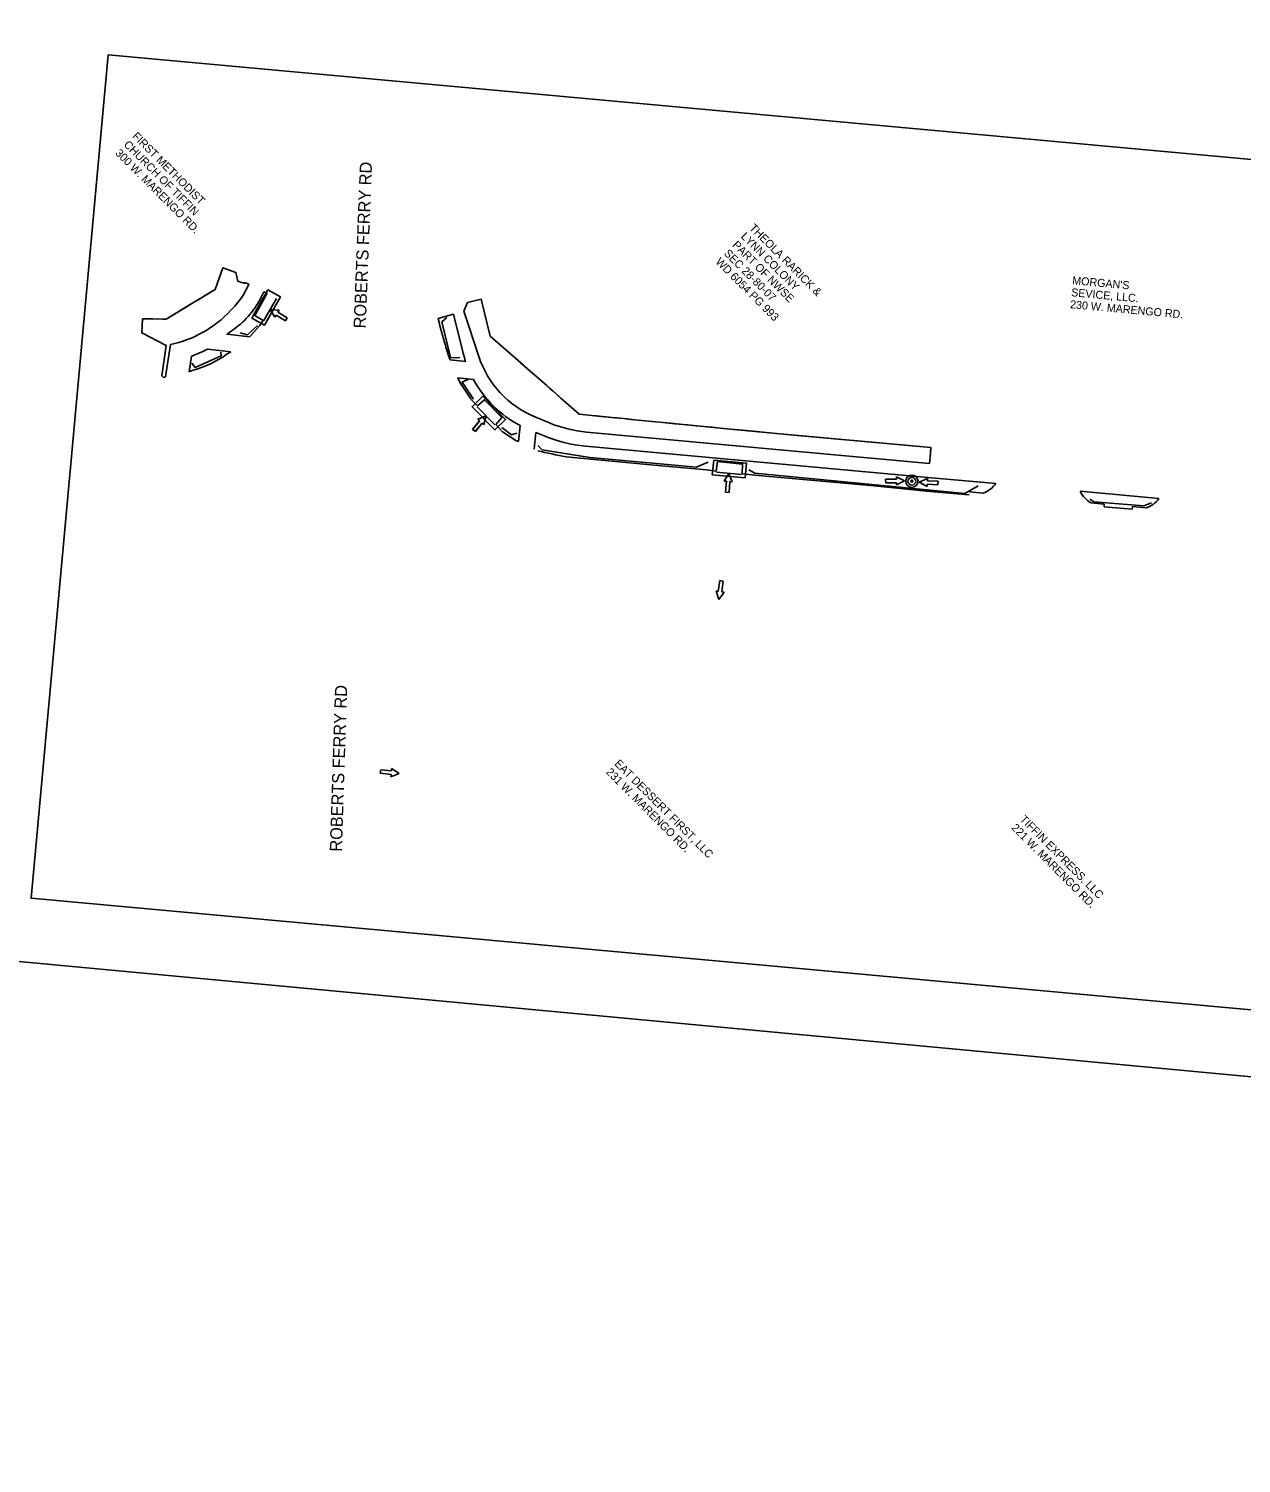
# Model space of a CAD drawing. Extents: x 20499351 to 20505779, y 7953198 to 7954637.
# Drawn here: x 20499884 to 20500313, y 7953707 to 7954215 of the extents above; entities that cross this region are included whole.
import ezdxf

# ---------------------------------------------------------------- set-up
doc = ezdxf.new("R2010")
doc.units = 0
for name, color, linetype in [('Draft_DNC', 7, 'Continuous'), ('dsnCellElements', 7, 'Continuous'), ('ErosionControl', 7, 'Continuous'), ('NamedBoundary', 7, 'Continuous'), ('Seeding', 7, 'Continuous'), ('Text', 7, 'Continuous')]:
    doc.layers.add(name, color=color, linetype=linetype)

msp = doc.modelspace()

# ---------------------------------------------------------------- linework, layer by layer
at = {"layer": 'Draft_DNC'}
msp.add_lwpolyline([(20501791.06, 7953833.84), (20501779.66, 7953706.56), (20499351.13, 7953933.78), (20499411.85, 7954636.65), (20501855.07, 7954405.25), (20501814.1, 7954091.19), (20501791.1, 7953834.34)], dxfattribs=at)
at = {"layer": 'dsnCellElements'}
for p, q in [((20499970.77, 7954112.56), (20499969.06, 7954115.26)), ((20499969.06, 7954115.26), (20499972.25, 7954115.01)), ((20499971.18, 7954113.24), (20499970.77, 7954112.56)), ((20499974.45, 7954111.26), (20499971.18, 7954113.24)), ((20499972.25, 7954115.01), (20499971.84, 7954114.33)), ((20499971.84, 7954114.33), (20499975.11, 7954112.35)), ((20499975.11, 7954112.35), (20499974.45, 7954111.26)), ((20500042.6, 7954076.28), (20500045.51, 7954077.59)), ((20500042.63, 7954076.37), (20500045.57, 7954077.65)), ((20500045.51, 7954077.59), (20500044.81, 7954074.47)), ((20500045.57, 7954077.65), (20500044.83, 7954074.53)), ((20500040.79, 7954072.94), (20500043.24, 7954075.86)), ((20500041.76, 7954072.12), (20500040.79, 7954072.94)), ((20500040.8, 7954072.82), (20500043.21, 7954075.77)), ((20500041.79, 7954072.01), (20500040.8, 7954072.82)), ((20500044.22, 7954075.04), (20500041.76, 7954072.12)), ((20500044.2, 7954074.97), (20500041.79, 7954072.01)), ((20500043.21, 7954075.77), (20500042.6, 7954076.28)), ((20500043.24, 7954075.86), (20500042.63, 7954076.37)), ((20500044.81, 7954074.47), (20500044.2, 7954074.97)), ((20500044.83, 7954074.53), (20500044.22, 7954075.04)), ((20500129.92, 7954054.47), (20500131.56, 7954057.22)), ((20500131.56, 7954057.22), (20500132.77, 7954054.26)), ((20500130.71, 7954054.41), (20500129.92, 7954054.47)), ((20500130.42, 7954050.61), (20500130.71, 7954054.41)), ((20500131.98, 7954054.32), (20500131.69, 7954050.51)), ((20500132.77, 7954054.26), (20500131.98, 7954054.32)), ((20500187.14, 7954055.13), (20500190.95, 7954055.2)), ((20500187.16, 7954053.86), (20500187.14, 7954055.13)), ((20500190.97, 7954053.92), (20500187.16, 7954053.86)), ((20500190.94, 7954055.99), (20500193.83, 7954054.61)), ((20500190.95, 7954055.2), (20500190.94, 7954055.99)), ((20500190.99, 7954053.13), (20500190.97, 7954053.92)), ((20500193.83, 7954054.61), (20500190.99, 7954053.13)), ((20500199.03, 7954054.12), (20500201.95, 7954055.43)), ((20500201.83, 7954052.57), (20500199.03, 7954054.12)), ((20500201.86, 7954053.37), (20500201.83, 7954052.57)), ((20500205.67, 7954053.21), (20500201.86, 7954053.37)), ((20500201.95, 7954055.43), (20500201.91, 7954054.64)), ((20500201.91, 7954054.64), (20500205.73, 7954054.48)), ((20500205.73, 7954054.48), (20500205.67, 7954053.21)), ((20500131.69, 7954050.51), (20500130.42, 7954050.61)), ((20500127.83, 7954015.45), (20500128.33, 7954019.23)), ((20500128.33, 7954019.23), (20500129.59, 7954019.06)), ((20500129.59, 7954019.06), (20500129.09, 7954015.28)), ((20500128.08, 7954012.53), (20500127.04, 7954015.55)), ((20500127.04, 7954015.55), (20500127.83, 7954015.45)), ((20500129.88, 7954015.18), (20500128.08, 7954012.53)), ((20500129.09, 7954015.28), (20500129.88, 7954015.18)), ((20500008.1, 7953951), (20500008.24, 7953952.26)), ((20500011.89, 7953950.58), (20500008.1, 7953951)), ((20500008.24, 7953952.26), (20500012.03, 7953951.84)), ((20500014.81, 7953950.9), (20500011.8, 7953949.79)), ((20500011.8, 7953949.79), (20500011.89, 7953950.58)), ((20500012.03, 7953951.84), (20500012.12, 7953952.63)), ((20500012.12, 7953952.63), (20500014.81, 7953950.9))]:
    msp.add_line(p, q, dxfattribs=at)
at = {"layer": 'ErosionControl'}
for p, q in [((20499961.16, 7954123.52), (20499961.48, 7954124.24)), ((20499966.43, 7954120.77), (20499966.78, 7954121.56)), ((20499966.78, 7954121.56), (20499968.01, 7954121.01)), ((20499971.29, 7954119.15), (20499966.84, 7954111.38)), ((20499955.04, 7954114.91), (20499956.53, 7954116.5)), ((20500028.62, 7954112.09), (20500033.97, 7954113.6)), ((20500037.46, 7954099.8), (20500033.97, 7954113.6)), ((20500033.97, 7954113.6), (20500037.46, 7954099.8)), ((20500043, 7954098.63), (20500037.71, 7954114.69)), ((20499932.05, 7954091.4), (20499933.71, 7954102.88)), ((20499933.71, 7954102.88), (20499932.05, 7954091.4)), ((20499941.2, 7954098.76), (20499940.4, 7954093.25)), ((20499955.15, 7954100.28), (20499946.86, 7954101.23)), ((20499946.86, 7954101.23), (20499955.15, 7954100.28)), ((20500032.84, 7954097.43), (20500032.54, 7954098.2)), ((20500038.34, 7954096.8), (20500032.84, 7954097.43)), ((20499940.4, 7954093.25), (20499941.42, 7954093.64)), ((20499941.42, 7954093.64), (20499940.4, 7954093.25)), ((20499932.05, 7954091.4), (20499931.33, 7954091.18)), ((20500036.44, 7954089.34), (20500035.55, 7954091.08)), ((20500041.12, 7954090.44), (20500035.55, 7954091.08)), ((20500042.48, 7954081.13), (20500040.14, 7954083.57)), ((20500040.14, 7954083.57), (20500042.48, 7954081.13)), ((20500048.68, 7954074.46), (20500042.46, 7954080.84)), ((20500068.03, 7954075.1), (20500062.84, 7954077.25)), ((20500057, 7954068.52), (20500057.61, 7954074.18)), ((20500063.18, 7954071.7), (20500062.55, 7954065.83)), ((20500066.12, 7954070.48), (20500063.18, 7954071.7)), ((20500066.12, 7954070.48), (20500063.18, 7954071.7)), ((20500202.65, 7954060.78), (20500081.18, 7954071.85)), ((20500202.05, 7954055.82), (20500080.74, 7954066.87)), ((20500202.76, 7954061.85), (20500202.65, 7954060.78)), ((20500136.05, 7954056.79), (20500127.22, 7954057.7)), ((20500226.17, 7954053.62), (20500202.05, 7954055.82)), ((20500201.61, 7954050.95), (20500216.77, 7954049.63)), ((20500216.85, 7954050.63), (20500221.68, 7954050.21)), ((20500256.04, 7954050.87), (20500283.97, 7954048.3)), ((20500264.61, 7954046.35), (20500259.89, 7954046.76)), ((20500274.52, 7954044.51), (20500264.52, 7954045.36)), ((20500279.54, 7954045.03), (20500274.61, 7954045.45))]:
    msp.add_line(p, q, dxfattribs=at)
for points in [[(20499931.33, 7954091.18), (20499930.64, 7954091.73), (20499932.26, 7954102.58), (20499923.57, 7954106.97), (20499923.9, 7954111.96), (20499932.19, 7954111.86), (20499936.85, 7954114.68), (20499940.55, 7954116.91), (20499944.11, 7954119.05), (20499945.84, 7954120.1), (20499947.93, 7954121.36), (20499949.54, 7954122.33), (20499952.26, 7954130.07), (20499956.97, 7954128.41), (20499957.58, 7954125.3), (20499958.93, 7954124.81), (20499959.55, 7954124.7), (20499959.85, 7954124.53), (20499960.13, 7954124.84), (20499961.47, 7954124.25)], [(20499968.01, 7954121.01), (20499963.61, 7954113.2), (20499966.58, 7954111.4)], [(20500037.71, 7954114.69), (20500039, 7954117.73), (20500043.86, 7954118.89), (20500046.99, 7954105.86), (20500054.19, 7954099.56), (20500058.66, 7954095.65), (20500065.77, 7954089.43), (20500068.3, 7954087.22), (20500069.35, 7954086.3), (20500070.87, 7954084.98), (20500072.09, 7954083.91), (20500078.6, 7954078.22), (20500083.09, 7954077.76), (20500086.33, 7954077.43), (20500088.94, 7954077.16), (20500091.19, 7954076.94), (20500091.91, 7954076.86), (20500094.21, 7954076.63), (20500097, 7954076.35), (20500100.74, 7954075.98), (20500105.59, 7954075.5), (20500111, 7954074.96), (20500115.39, 7954074.53), (20500121.42, 7954073.95), (20500128.45, 7954073.27), (20500135.78, 7954072.57), (20500147.21, 7954071.5), (20500203.2, 7954066.35), (20500203.06, 7954064.92), (20500202.86, 7954062.84), (20500202.75, 7954061.85), (20500202.76, 7954061.85)], [(20500031.72, 7954112.5), (20500029.87, 7954110.88), (20500033.02, 7954098.33), (20500036.24, 7954098.12)], [(20499961.73, 7954105.57), (20499953.82, 7954106.48), (20499957.03, 7954108.89)], [(20499958.39, 7954107.05), (20499961.03, 7954106.31), (20499964.61, 7954109.64)], [(20499966.58, 7954111.4), (20499965.38, 7954109.56), (20499962.15, 7954105.96), (20499961.73, 7954105.57)], [(20499941.29, 7954096.26), (20499942.55, 7954094.7), (20499951.74, 7954098.89), (20499951.64, 7954100.18)], [(20499953.87, 7954099.52), (20499954.99, 7954100.19), (20499955.12, 7954100.29)], [(20500039.37, 7954090.6), (20500037.08, 7954089.51), (20500041.15, 7954083.54)], [(20500042.48, 7954081.13), (20500045.03, 7954083.31), (20500051.14, 7954077.06), (20500049, 7954074.51)], [(20500049, 7954074.51), (20500051.43, 7954071.95), (20500056.15, 7954068.91), (20500057, 7954068.52)], [(20500051.11, 7954073.53), (20500054.61, 7954070.93), (20500056.44, 7954071.5)], [(20500063.92, 7954067.15), (20500065.41, 7954065.59), (20500082.38, 7954062.87), (20500109.87, 7954060.35), (20500120.05, 7954059.46), (20500124.2, 7954061.22)], [(20500073.94, 7954063.07), (20500103.94, 7954060.2), (20500123.68, 7954058.43), (20500127.04, 7954058.06)], [(20500127.04, 7954058.06), (20500127.52, 7954061.41), (20500136.42, 7954060.54), (20500136.28, 7954057.11)], [(20500136.28, 7954057.11), (20500143.33, 7954056.36), (20500183.05, 7954052.76), (20500201.61, 7954050.95)], [(20500138.72, 7954058.46), (20500140.82, 7954057.3), (20500215.22, 7954050.15), (20500219.97, 7954052.8)], [(20500259.44, 7954048.12), (20500260.95, 7954047.15), (20500278.64, 7954045.76), (20500281.36, 7954046.81)]]:
    msp.add_lwpolyline(points, dxfattribs=at)
for points in [[(20499968.23, 7954122.26), (20499962.59, 7954112.25), (20499967.04, 7954109.75), (20499972.68, 7954119.75)], [(20500044.42, 7954084.52), (20500052.46, 7954076.29), (20500048.69, 7954072.6), (20500040.64, 7954080.84)], [(20500126.22, 7954061.95), (20500137.84, 7954060.81), (20500137.33, 7954055.6), (20500125.71, 7954056.74)]]:
    msp.add_lwpolyline(points, close=True, dxfattribs=at)
for radius in [2.19, 1.38, 1.38, 0.333]:
    msp.add_circle((20500196.42, 7954054.44), radius, dxfattribs=at)
for centre, radius, start, end in [((20499938.28, 7954133.59), 25, 316.8794, 338.0615), ((20499938.28, 7954133.59), 25, 316.8794, 336.2589), ((20499938.97, 7954132.85), 30, 307.0003, 336.2589), ((20499925.67, 7954142.06), 40, 281.6016, 317.2577), ((20499925.67, 7954142.06), 40, 281.6016, 317.2577), ((20499925.67, 7954142.06), 46, 289.7337, 297.437), ((20499925.67, 7954142.06), 46, 289.7337, 297.437), ((20500076.24, 7954109.58), 40, 194.1598, 198.6373), ((20500076.24, 7954109.58), 35, 198.233, 247.4817), ((20500076.24, 7954109.58), 40, 208.5871, 242.24), ((20500085.27, 7954116.67), 45, 247.4817, 264.7944), ((20500085.27, 7954116.67), 50, 247.4814, 264.8052), ((20500085.27, 7954116.67), 50, 247.4814, 264.8052), ((20500218.11, 7954059.55), 10, 290.8655, 323.6405), ((20500264.98, 7954055.36), 10, 206.6445, 239.2845), ((20500276.04, 7954054.39), 10, 290.563, 322.4475)]:
    msp.add_arc(centre, radius, start, end, dxfattribs=at)
for centre, major_axis, ratio, start_param, end_param in [((20499930.7, 7954132.48), (40.08, -4.21), 0.999939, 5.086579, 5.429975), ((20499930.7, 7954132.48), (40.08, -4.21), 0.999939, 5.086579, 5.429975), ((20500101.16, 7954128.32), (47.26, -79.5), 0.816879, 4.717117, 4.7912), ((20500101.16, 7954128.32), (47.26, -79.5), 0.816879, 4.717117, 4.7912), ((20500118.18, 7954291.91), (234.67, -29.43), 0.985398, 4.603689, 4.647146)]:
    msp.add_ellipse(centre, major_axis=major_axis, ratio=ratio, start_param=start_param, end_param=end_param, dxfattribs=at)
msp.add_open_spline([(20500032.54, 7954098.2), (20500032.12, 7954099.31), (20500030.86, 7954103.62), (20500029.54, 7954108.18), (20500028.72, 7954111.66), (20500028.62, 7954112.09)], degree=3, dxfattribs=at)
msp.add_open_spline([(20500032.54, 7954098.2), (20500032.12, 7954099.31), (20500030.86, 7954103.62), (20500029.54, 7954108.18), (20500028.72, 7954111.66), (20500028.62, 7954112.09)], degree=3, dxfattribs=at)
at = {"layer": 'NamedBoundary'}
msp.add_lwpolyline([(20499911.73, 7954205.45), (20499884.39, 7953906.7), (20500820.97, 7953820.99), (20500848.31, 7954119.74)], close=True, dxfattribs=at)
at = {"layer": 'Seeding'}
for p, q in [((20499961.16, 7954123.52), (20499961.48, 7954124.24)), ((20499966.43, 7954120.77), (20499966.78, 7954121.56)), ((20499966.78, 7954121.56), (20499968.01, 7954121.01)), ((20499955.04, 7954114.91), (20499956.53, 7954116.5)), ((20500028.62, 7954112.09), (20500033.97, 7954113.6)), ((20500037.46, 7954099.8), (20500033.97, 7954113.6)), ((20500033.97, 7954113.6), (20500037.46, 7954099.8)), ((20500043, 7954098.63), (20500037.71, 7954114.69)), ((20499932.05, 7954091.4), (20499933.71, 7954102.88)), ((20499933.71, 7954102.88), (20499932.05, 7954091.4)), ((20499941.2, 7954098.76), (20499940.4, 7954093.25)), ((20499955.15, 7954100.28), (20499946.86, 7954101.23)), ((20499946.86, 7954101.23), (20499955.15, 7954100.28)), ((20500032.84, 7954097.43), (20500032.54, 7954098.2)), ((20500038.34, 7954096.8), (20500032.84, 7954097.43)), ((20499940.4, 7954093.25), (20499941.42, 7954093.64)), ((20499941.42, 7954093.64), (20499940.4, 7954093.25)), ((20499932.05, 7954091.4), (20499931.33, 7954091.18)), ((20500036.44, 7954089.34), (20500035.55, 7954091.08)), ((20500041.12, 7954090.44), (20500035.55, 7954091.08)), ((20500042.48, 7954081.13), (20500040.14, 7954083.57)), ((20500040.14, 7954083.57), (20500042.48, 7954081.13)), ((20500068.03, 7954075.1), (20500062.84, 7954077.25)), ((20500057, 7954068.52), (20500057.61, 7954074.18)), ((20500063.18, 7954071.7), (20500062.55, 7954065.83)), ((20500066.12, 7954070.48), (20500063.18, 7954071.7)), ((20500066.12, 7954070.48), (20500063.18, 7954071.7)), ((20500202.65, 7954060.78), (20500081.18, 7954071.85)), ((20500202.05, 7954055.82), (20500080.74, 7954066.87)), ((20500202.76, 7954061.85), (20500202.65, 7954060.78)), ((20500226.17, 7954053.62), (20500202.05, 7954055.82)), ((20500201.61, 7954050.95), (20500216.77, 7954049.63)), ((20500216.85, 7954050.63), (20500221.68, 7954050.21)), ((20500256.04, 7954050.87), (20500283.97, 7954048.3)), ((20500259.89, 7954046.76), (20500264.61, 7954046.35)), ((20500264.61, 7954046.35), (20500259.89, 7954046.76)), ((20500264.61, 7954046.35), (20500264.52, 7954045.36)), ((20500274.52, 7954044.51), (20500264.52, 7954045.36)), ((20500274.52, 7954044.49), (20500274.61, 7954045.45)), ((20500274.61, 7954045.45), (20500279.54, 7954045.03)), ((20500279.54, 7954045.03), (20500274.61, 7954045.45))]:
    msp.add_line(p, q, dxfattribs=at)
for points in [[(20499931.33, 7954091.18), (20499930.64, 7954091.73), (20499932.26, 7954102.58), (20499923.57, 7954106.97), (20499923.9, 7954111.96), (20499927.51, 7954111.92), (20499930.91, 7954111.88), (20499932.19, 7954111.86), (20499939.11, 7954116.04), (20499941.94, 7954117.74), (20499946.88, 7954120.73), (20499949.54, 7954122.33), (20499952.26, 7954130.07), (20499956.97, 7954128.41), (20499957.58, 7954125.3), (20499958.93, 7954124.81), (20499959.55, 7954124.7), (20499959.85, 7954124.53), (20499960.13, 7954124.84), (20499961.47, 7954124.25)], [(20499968.01, 7954121.01), (20499963.61, 7954113.2), (20499966.58, 7954111.4)], [(20500037.71, 7954114.69), (20500039, 7954117.73), (20500043.86, 7954118.89), (20500046.99, 7954105.86), (20500050.59, 7954102.71), (20500057.7, 7954096.49), (20500067.04, 7954088.32), (20500072.57, 7954083.49), (20500078.6, 7954078.22), (20500083.09, 7954077.76), (20500084.71, 7954077.59), (20500090.07, 7954077.05), (20500095.61, 7954076.49), (20500098.11, 7954076.24), (20500100.74, 7954075.98), (20500105.59, 7954075.5), (20500108.29, 7954075.23), (20500112.39, 7954074.83), (20500116.9, 7954074.39), (20500120.05, 7954074.08), (20500125.64, 7954073.54), (20500128.45, 7954073.27), (20500133.63, 7954072.78), (20500137.79, 7954072.38), (20500142.57, 7954071.93), (20500145.95, 7954071.62), (20500155.88, 7954070.7), (20500203.2, 7954066.35), (20500203.01, 7954064.34), (20500202.86, 7954062.84), (20500202.75, 7954061.85), (20500202.76, 7954061.85)], [(20499961.73, 7954105.57), (20499953.82, 7954106.48), (20499957.03, 7954108.89)], [(20499966.58, 7954111.4), (20499965.38, 7954109.56), (20499962.15, 7954105.96), (20499961.73, 7954105.57)], [(20499953.87, 7954099.52), (20499954.99, 7954100.19), (20499955.12, 7954100.29)], [(20500042.48, 7954081.13), (20500045.03, 7954083.31), (20500051.14, 7954077.06), (20500049, 7954074.51)], [(20500049, 7954074.51), (20500051.43, 7954071.95), (20500056.15, 7954068.91), (20500057, 7954068.52)], [(20500073.94, 7954063.07), (20500103.94, 7954060.2), (20500123.68, 7954058.43), (20500127.04, 7954058.06)], [(20500127.04, 7954058.06), (20500127.52, 7954061.41), (20500136.42, 7954060.54), (20500136.28, 7954057.11)], [(20500136.28, 7954057.11), (20500143.33, 7954056.36), (20500183.05, 7954052.76), (20500201.61, 7954050.95)]]:
    msp.add_lwpolyline(points, dxfattribs=at)
for centre, radius, start, end in [((20499938.28, 7954133.59), 25, 316.8794, 338.0615), ((20499938.28, 7954133.59), 25, 316.8794, 336.2589), ((20499938.97, 7954132.85), 30, 307.0003, 336.2589), ((20499925.67, 7954142.06), 40, 281.6016, 317.2577), ((20499925.67, 7954142.06), 40, 281.6016, 317.2577), ((20499925.67, 7954142.06), 46, 289.7337, 297.437), ((20499925.67, 7954142.06), 46, 289.7337, 297.437), ((20500076.24, 7954109.58), 40, 194.1598, 198.6373), ((20500076.24, 7954109.58), 35, 198.233, 247.4817), ((20500076.24, 7954109.58), 40, 208.5871, 242.24), ((20500085.27, 7954116.67), 45, 247.4817, 264.7944), ((20500085.27, 7954116.67), 50, 247.4814, 264.8052), ((20500085.27, 7954116.67), 50, 247.4814, 264.8052), ((20500218.11, 7954059.55), 10, 290.8655, 323.6405), ((20500264.98, 7954055.36), 10, 206.6445, 239.2845), ((20500264.98, 7954055.36), 10, 206.6445, 239.2845), ((20500276.04, 7954054.39), 10, 290.563, 322.4475), ((20500276.04, 7954054.39), 10, 290.563, 322.4475)]:
    msp.add_arc(centre, radius, start, end, dxfattribs=at)
for centre, major_axis, ratio, start_param, end_param in [((20499930.7, 7954132.48), (40.08, -4.21), 0.999939, 5.086579, 5.429975), ((20499930.7, 7954132.48), (40.08, -4.21), 0.999939, 5.086579, 5.429975), ((20500101.16, 7954128.32), (47.26, -79.5), 0.816879, 4.717117, 4.7912), ((20500101.16, 7954128.32), (47.26, -79.5), 0.816879, 4.717117, 4.7912), ((20500118.18, 7954291.91), (234.67, -29.43), 0.985398, 4.603689, 4.647146)]:
    msp.add_ellipse(centre, major_axis=major_axis, ratio=ratio, start_param=start_param, end_param=end_param, dxfattribs=at)
msp.add_open_spline([(20500032.54, 7954098.2), (20500032.12, 7954099.31), (20500030.86, 7954103.62), (20500029.54, 7954108.18), (20500028.72, 7954111.66), (20500028.62, 7954112.09)], degree=3, dxfattribs=at)
msp.add_open_spline([(20500032.54, 7954098.2), (20500032.12, 7954099.31), (20500030.86, 7954103.62), (20500029.54, 7954108.18), (20500028.72, 7954111.66), (20500028.62, 7954112.09)], degree=3, dxfattribs=at)

# ---------------------------------------------------------------- texts
at = {"layer": 'Text'}
for s, height, rotation, p in [('CHURCH OF TIFFIN', 2.8346, 314.9836, (20499916.99, 7954173.44)), ('FIRST METHODIST', 2.8346, 314.9836, (20499919.99, 7954176.45)), ('300 W. MARENGO RD.', 2.8346, 314.9836, (20499913.98, 7954170.43)), ('ROBERTS FERRY RD', 4.32, 87.7944, (20500002.92, 7954108.52)), ('THEOLA RARICK &', 2.8346, 314.9836, (20500138.66, 7954143.94)), ('PART OF NWSE', 2.8346, 314.9836, (20500132.65, 7954137.93)), ('LYNN COLONY', 2.8346, 314.9836, (20500135.65, 7954140.94)), ('WD 6054 PG 993', 2.8346, 314.9836, (20500126.63, 7954131.92)), ('SEC 28-80-07', 2.8346, 314.9836, (20500129.64, 7954134.92)), ('SEVICE, LLC.', 2.8346, 354.7645, (20500252.76, 7954120)), ("MORGAN'S ", 2.835, 354.7645, (20500253.15, 7954124.24)), ('230 W. MARENGO RD.', 2.8346, 354.7645, (20500252.38, 7954115.77)), ('ROBERTS FERRY RD', 4.32, 88.1425, (20499994.49, 7953923.16)), ('EAT DESSERT FIRST, LLC', 2.8346, 314.9836, (20500090.86, 7953954.19)), ('231 W. MARENGO RD.', 2.8346, 314.9836, (20500087.85, 7953951.18)), ('TIFFIN EXPRESS, LLC', 2.8346, 314.9836, (20500234.46, 7953934.46)), ('221 W. MARENGO RD.', 2.8346, 314.9836, (20500231.46, 7953931.46))]:
    msp.add_text(s, height=height, rotation=rotation, dxfattribs=at).set_placement(p)

doc.saveas('drawing.dxf')
